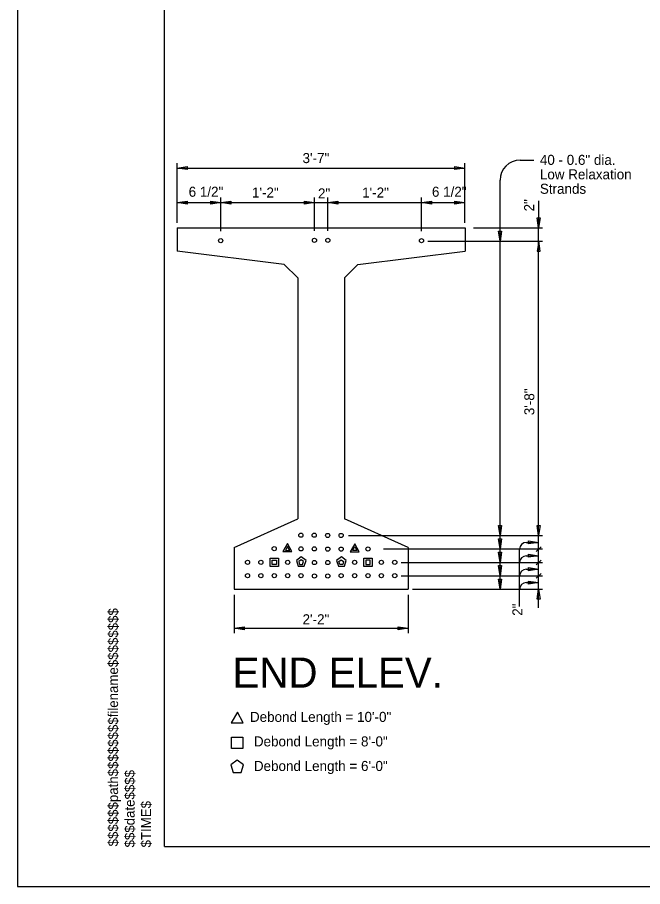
# Model space of a CAD drawing. Extents: x -125.5 to -89.3, y 42.4 to 64.4.
# Drawn here: x -125.53 to -117.75, y 42.45 to 53.27 of the extents above; entities that cross this region are included whole.
import ezdxf

# ---------------------------------------------------------------- set-up
doc = ezdxf.new("R2010")
doc.units = 0
for name, color, linetype in [('BR_AUTO DIMENSION', 7, 'Continuous'), ('BR_BORDER LINES', 7, 'Continuous'), ('BR_PRESTRESSED BEAM', 7, 'Continuous'), ('BR_REBAR', 7, 'Continuous'), ('Level 31', 7, 'Continuous'), ('RD_SHT_ID', 7, 'Continuous')]:
    doc.layers.add(name, color=color, linetype=linetype)

msp = doc.modelspace()

# ---------------------------------------------------------------- linework, layer by layer
at = {"layer": 'BR_AUTO DIMENSION'}
for p, q in [((-123.542, 50.712), (-123.542, 51.455)), ((-119.961, 50.712), (-119.961, 51.455)), ((-119.273, 51.492), (-119.102, 51.492)), ((-123.542, 51.393), (-119.961, 51.393)), ((-119.523, 46.985), (-119.523, 51.242)), ((-123.001, 50.608), (-123.001, 51.026)), ((-121.834, 50.612), (-121.834, 51.026)), ((-121.669, 50.612), (-121.669, 51.026)), ((-120.502, 50.608), (-120.502, 51.026)), ((-119.043, 50.984), (-119.043, 50.65)), ((-123.542, 50.964), (-119.961, 50.964)), ((-119.854, 50.65), (-118.993, 50.65)), ((-119.043, 46.985), (-119.043, 50.65)), ((-120.422, 50.483), (-118.993, 50.483)), ((-119.523, 46.152), (-119.523, 46.985)), ((-119.043, 46.15), (-119.043, 46.985)), ((-121.409, 46.819), (-118.993, 46.819)), ((-120.975, 46.652), (-118.993, 46.652)), ((-119.279, 45.934), (-119.279, 46.65)), ((-119.196, 46.733), (-119.043, 46.733)), ((-119.072, 46.62), (-119.013, 46.679)), ((-119.196, 46.566), (-119.043, 46.566)), ((-120.756, 46.485), (-118.993, 46.485)), ((-119.072, 46.454), (-119.013, 46.513)), ((-120.756, 46.319), (-118.993, 46.319)), ((-119.196, 46.4), (-119.043, 46.4)), ((-119.072, 46.287), (-119.013, 46.346)), ((-119.196, 46.233), (-119.043, 46.233)), ((-120.614, 46.15), (-118.993, 46.15)), ((-119.043, 45.92), (-119.043, 46.15)), ((-122.833, 46.079), (-122.833, 45.603)), ((-120.666, 46.079), (-120.666, 45.603)), ((-122.833, 45.666), (-120.666, 45.666))]:
    msp.add_line(p, q, dxfattribs=at)
for points in [[(-123.417, 51.374), (-123.542, 51.393), (-123.417, 51.411)], [(-120.086, 51.411), (-119.961, 51.393), (-120.086, 51.374)], [(-123.417, 50.945), (-123.542, 50.964), (-123.417, 50.983)], [(-123.126, 50.983), (-123.001, 50.964), (-123.126, 50.945)], [(-122.876, 50.945), (-123.001, 50.964), (-122.876, 50.983)], [(-121.959, 50.983), (-121.834, 50.964), (-121.959, 50.945)], [(-121.544, 50.945), (-121.669, 50.964), (-121.544, 50.983)], [(-120.377, 50.945), (-120.502, 50.964), (-120.377, 50.983)], [(-120.086, 50.983), (-119.961, 50.964), (-120.086, 50.945)], [(-119.024, 50.775), (-119.043, 50.65), (-119.061, 50.775)], [(-119.504, 50.608), (-119.523, 50.483), (-119.542, 50.608)], [(-119.024, 50.359), (-119.042, 50.484), (-119.061, 50.359)], [(-119.504, 46.944), (-119.523, 46.819), (-119.542, 46.944)], [(-119.024, 46.944), (-119.043, 46.819), (-119.061, 46.944)], [(-119.504, 46.777), (-119.523, 46.652), (-119.542, 46.777)], [(-119.168, 46.752), (-119.043, 46.733), (-119.168, 46.714)], [(-119.504, 46.61), (-119.523, 46.485), (-119.542, 46.61)], [(-119.168, 46.585), (-119.043, 46.566), (-119.168, 46.548)], [(-119.504, 46.444), (-119.523, 46.319), (-119.542, 46.444)], [(-119.168, 46.419), (-119.043, 46.4), (-119.168, 46.381)], [(-119.504, 46.277), (-119.523, 46.152), (-119.542, 46.277)], [(-119.168, 46.252), (-119.043, 46.233), (-119.168, 46.214)], [(-119.061, 46.025), (-119.043, 46.15), (-119.024, 46.025)], [(-122.708, 45.647), (-122.833, 45.666), (-122.708, 45.684)], [(-120.791, 45.684), (-120.666, 45.666), (-120.791, 45.647)]]:
    msp.add_lwpolyline(points, close=True, dxfattribs=at)
for centre, radius in [((-119.273, 51.242), 0.25), ((-119.196, 46.65), 0.0833), ((-119.196, 46.483), 0.0833), ((-119.196, 46.316), 0.0833), ((-119.196, 46.15), 0.0833)]:
    msp.add_arc(centre, radius, 90, 180, dxfattribs=at)
at = {"layer": 'BR_BORDER LINES'}
for q in [(-123.699, 63.949), (-90.033, 42.949)]:
    msp.add_line((-123.699, 42.949), q, dxfattribs=at)
at = {"layer": 'BR_PRESTRESSED BEAM'}
for p, q in [((-123.542, 50.65), (-123.542, 50.358)), ((-123.542, 50.65), (-119.959, 50.65)), ((-119.959, 50.65), (-119.959, 50.358)), ((-122.209, 50.191), (-123.542, 50.358)), ((-121.292, 50.191), (-119.959, 50.358)), ((-122.042, 50.025), (-122.209, 50.191)), ((-121.459, 50.025), (-121.292, 50.191)), ((-122.042, 50.025), (-122.042, 47.025)), ((-121.459, 50.025), (-121.459, 47.025)), ((-122.834, 46.671), (-122.042, 47.025)), ((-120.667, 46.671), (-121.459, 47.025)), ((-122.834, 46.671), (-122.834, 46.15)), ((-120.667, 46.671), (-120.667, 46.15)), ((-122.834, 46.15), (-120.667, 46.15))]:
    msp.add_line(p, q, dxfattribs=at)
at = {"layer": 'BR_REBAR'}
for points in [[(-122.226, 46.619), (-122.115, 46.619), (-122.17, 46.718)], [(-122.196, 46.633), (-122.141, 46.633), (-122.168, 46.681)], [(-121.389, 46.616), (-121.277, 46.616), (-121.332, 46.715)], [(-121.305, 46.633), (-121.36, 46.633), (-121.333, 46.681)], [(-122.387, 46.433), (-122.387, 46.538), (-122.281, 46.538), (-122.281, 46.433)], [(-121.938, 46.509), (-121.998, 46.553), (-122.058, 46.509), (-122.035, 46.438), (-121.961, 46.439)], [(-121.438, 46.509), (-121.498, 46.553), (-121.558, 46.509), (-121.535, 46.438), (-121.461, 46.439)], [(-121.22, 46.433), (-121.22, 46.538), (-121.115, 46.538), (-121.115, 46.433)], [(-122.36, 46.459), (-122.36, 46.511), (-122.308, 46.511), (-122.308, 46.459)], [(-121.971, 46.495), (-122.001, 46.516), (-122.03, 46.495), (-122.019, 46.46), (-121.982, 46.46)], [(-121.53, 46.495), (-121.501, 46.516), (-121.471, 46.495), (-121.482, 46.46), (-121.519, 46.46)], [(-121.141, 46.459), (-121.141, 46.511), (-121.193, 46.511), (-121.193, 46.459)], [(-122.869, 44.488), (-122.72, 44.488), (-122.793, 44.619)], [(-122.865, 44.166), (-122.865, 44.307), (-122.725, 44.307), (-122.725, 44.166)], [(-122.716, 43.965), (-122.796, 44.023), (-122.876, 43.964), (-122.845, 43.87), (-122.746, 43.87)]]:
    msp.add_lwpolyline(points, close=True, dxfattribs=at)
for centre in [(-123.001, 50.489), (-123.001, 50.489), (-121.834, 50.493), (-121.834, 50.493), (-121.667, 50.493), (-121.667, 50.493), (-120.501, 50.489), (-120.501, 50.489), (-122.003, 46.823), (-121.837, 46.823), (-121.669, 46.82), (-121.502, 46.82), (-122.335, 46.655), (-122.002, 46.653), (-121.836, 46.653), (-121.668, 46.65), (-121.501, 46.65), (-121.167, 46.652), (-122.667, 46.485), (-122.501, 46.485), (-122.167, 46.485), (-121.834, 46.483), (-121.668, 46.483), (-121.334, 46.485), (-121.001, 46.485), (-120.834, 46.485), (-122.667, 46.319), (-122.501, 46.319), (-122.334, 46.319), (-122.167, 46.319), (-122.001, 46.319), (-121.834, 46.316), (-121.668, 46.316), (-121.501, 46.319), (-121.334, 46.319), (-121.167, 46.319), (-121.001, 46.319), (-120.834, 46.319)]:
    msp.add_circle(centre, 0.026, dxfattribs=at)
at = {"layer": 'Level 31'}
msp.add_lwpolyline([(-125.533, 42.449), (-89.533, 42.449), (-89.533, 64.449), (-125.533, 64.449)], close=True, dxfattribs=at)

# ---------------------------------------------------------------- texts
at = {"layer": 'BR_AUTO DIMENSION'}
for s, height, p in [('3\'-7"', 0.125, (-121.982, 51.455)), ('40 - 0.6" dia.', 0.125, (-119.027, 51.433)), ('Low Relaxation', 0.125, (-119.027, 51.253)), ('Strands', 0.125, (-119.027, 51.073)), ('6 1/2"', 0.125, (-123.4, 51.036)), ('1\'-2"', 0.125, (-122.612, 51.026)), ('2"', 0.125, (-121.79, 51.015)), ('1\'-2"', 0.125, (-121.24, 51.026)), ('6 1/2"', 0.125, (-120.371, 51.036)), ('2\'-2"', 0.125, (-121.982, 45.714)), ('END ELEV.', 0.375, (-122.854, 44.925)), ('Debond Length = 10\'-0"', 0.125, (-122.637, 44.499)), ('Debond Length = 8\'-0"', 0.125, (-122.588, 44.194)), ('Debond Length = 6\'-0"', 0.125, (-122.588, 43.888))]:
    msp.add_text(s, height=height, dxfattribs=at).set_placement(p)
for s, p in [('2"', (-119.098, 50.854)), ('3\'-8"', (-119.096, 48.317)), ('2"', (-119.244, 45.82))]:
    msp.add_text(s, height=0.125, rotation=90, dxfattribs=at).set_placement(p)
at = {"layer": 'RD_SHT_ID'}
for s, height, p in [('$$$$$$path$$$$$$$$filename$$$$$$$$', 0.12347, (-124.279, 42.949)), ('$$$date$$$$', 0.12347, (-124.073, 42.936)), ('$TIME$', 0.1235, (-123.869, 42.936))]:
    msp.add_text(s, height=height, rotation=90, dxfattribs=at).set_placement(p)

doc.saveas('drawing.dxf')
